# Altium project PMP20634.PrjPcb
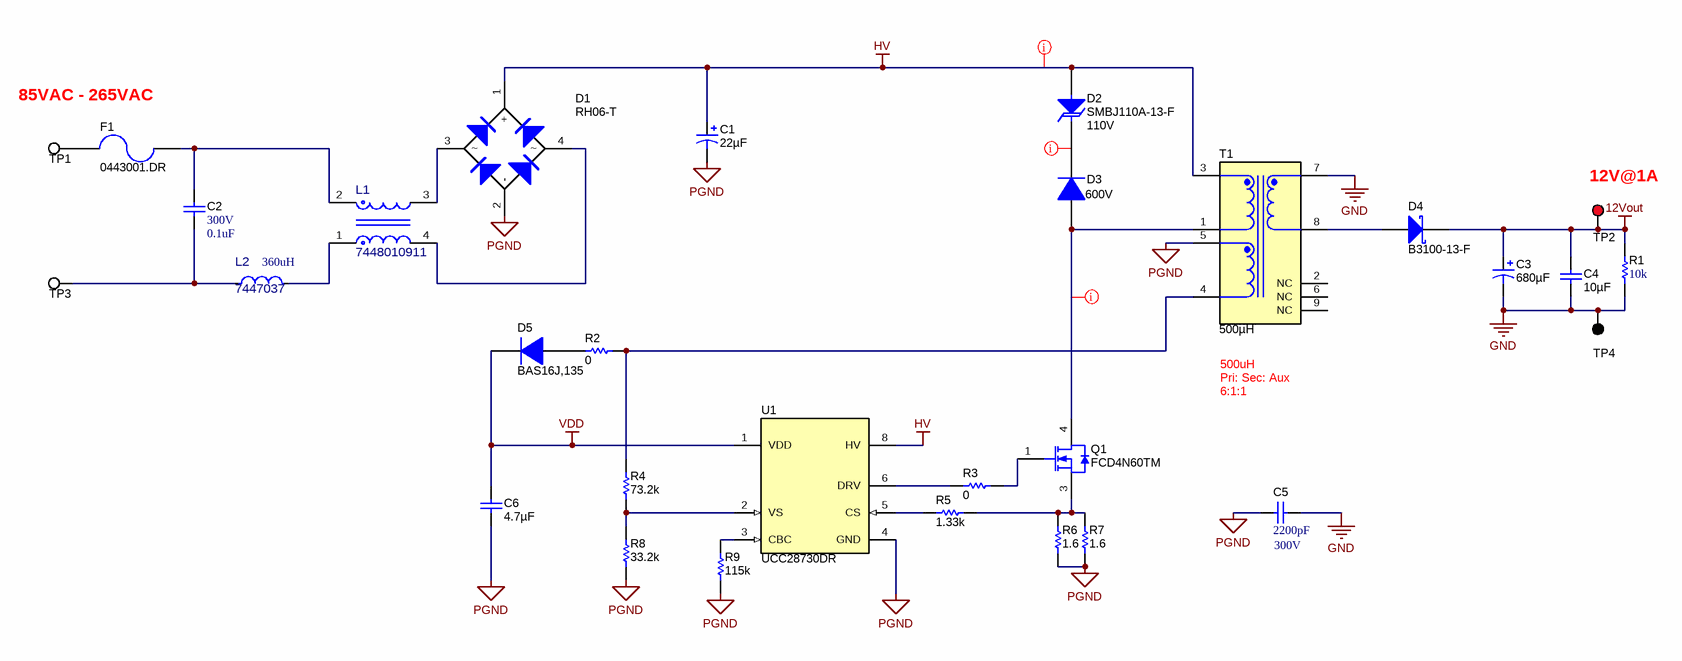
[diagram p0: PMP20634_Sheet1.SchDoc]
TID: N/A; TechSupport: http://www.ti.com/support; SCH_Rev: C; PRJ_Title: 85-265VAC to 12V@1A QR Flyback; PRJ_Number: PMP20634; PRJ_Engineer: C Sarli; PRJ_Customer: Public Release; PCB_Rev: C; PCB_Layout: C Sarli; CopyrightYear: 2016
1 sheet, 30 parts. Net scope: global (net labels, ports and power ports of the same name join across sheets).
Board file: PMP20634.PcbDoc

## Sheet PMP20634_Sheet1.SchDoc
size 431 x 279 mm; Date: Not shown in title block; ApprovedBy: Not shown in title block; CheckedBy: Not shown in title block; Author: Not shown in title block; CompanyName: Not shown in title block; Engineer: Not shown in title block; Organization: Not shown in title block; Address1: Not shown in title block; Address2: Not shown in title block; Address3: Not shown in title block; Address4: Not shown in title block; DocumentNumber: 1; Revision: Use project parameter SCH_Rev; SheetNumber: 1; SheetTotal: 1; PageSetup: Record=PageOptions¦CenterHorizontal=True¦CenterVertical=True¦PrintScale=1.00¦XCorrection=1.00¦YCorrection=1.00¦PrintKind=0¦BorderSize=5000000¦LeftOffset=0¦BottomOffset=0¦Orientation=2¦PaperLength=1000¦PaperWidth=1000¦Scale=100¦PaperSource=15¦PrintQuality=600¦MediaType=1¦DitherType=10¦PaperKind=Letter¦PrintScaleMode=1

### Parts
C1  ValueDisplayed: 22µF  [KXG_1250x2000]  (hidden comment: EKXG401ELL220MK20S)
C2  VDC_V: 300V  ValueDisplayed: 0.1uF  [ECQUG_1500x800x1500]  (hidden comment: ECQ-U3A104MG)
C3  ValueDisplayed: 680µF  [Chemi-Con_1000x2000]  (hidden comment: EKZE250ELL681MJ20S)
C4  ValueDisplayed: 10µF  [0805_HV]  (hidden comment: GRM219R61E106KA12)
C5  VDC_V: 300V  ValueDisplayed: 2200pF  [CAPRD500W60D900H1200]  (hidden comment: VY2222M35Y5US6UV5)
C6  ValueDisplayed: 4.7µF  [0603]  (hidden comment: GRM188R6YA475KE15D)
D1  RH06-T  [MiniDIP]
D2  SMBJ110A-13-F  value 110V  [SMB]
D3  Value2: 600V  [SMA]  (hidden comment: MURA160T3G)
D4  B3100-13-F  [SMC]
D5  BAS16J,135  [SOD-323F]
F1  0443001.DR  [FUSE_0443]
L1  7448010911  [FP-7448010911_PTH_CMC_14MM0_7MM5-MFG]
L2  7447037  value 360uH  [FP-7447037_RADIAL-MFG]
Q1  FCD4N60TM  [DPAK]
R1  ValueDisplayed: 10k  [1206]  (hidden comment: CRCW120610K0JNEA)
R2  ValueDisplayed: 0  [0402]  (hidden comment: CRCW04020000Z0ED)
R3  ValueDisplayed: 0  [0402]  (hidden comment: CRCW04020000Z0ED)
R4  ValueDisplayed: 73.2k  [0402]  (hidden comment: CRCW040273K2FKED)
R5  ValueDisplayed: 1.33k  [0402]  (hidden comment: CRCW04021K33FKED)
R6  ValueDisplayed: 1.6  [0805_HV]  (hidden comment: CRCW08051R60JNEA)
R7  ValueDisplayed: 1.6  [0805_HV]  (hidden comment: CRCW08051R60JNEA)
R8  ValueDisplayed: 33.2k  [0402]  (hidden comment: CRCW040233K2FKED)
R9  ValueDisplayed: 115k  [0402]  (hidden comment: CRCW0402115KFKED)
T1  ValueDisplayed: 500µH  [Wurth_EE16-8-5_5280]  (hidden comment: 750316686)
TP1  5012  [Keystone5012]  (value not drawn)
TP2  5010  [Keystone5010]  (value not drawn)
TP3  5012  [Keystone5012]  (value not drawn)
TP4  5011  [Keystone5011]  (value not drawn)
U1  UCC28730DR  [D0007A_N]

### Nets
12Vout: C3.1(+) C4.1 D4.1(K) R1.2 TP2.1
GND: C3.2(-) C4.2 C5.1 R1.1 T1.7 TP4.1
HV: C1.1(+) D1.1(+) D2.2(A) T1.3 U1.8(HV)
PGND: C1.2(-) C5.2 C6.2 D1.2(-) R6.1 R7.1 R8.1 R9.1 T1.5 U1.4(GND)
VDD: C6.1 D5.1(K) U1.1(VDD)
NetC2_1: C2.1 F1.1 L1.2
NetC2_2: C2.2 L2.1 TP3.1
NetD1_3: D1.3 L1.3
NetD1_4: D1.4 L1.4
NetD2_1: D2.1(K) D3.1(K)
NetD3_2: D3.2(A) Q1.4(D) T1.1
NetD4_2: D4.2(A) T1.8
NetD5_2: D5.2(A) R2.1
NetF1_2: F1.2 TP1.1
NetL1_1: L1.1 L2.2
NetQ1_1: Q1.1(G) R3.2
NetQ1_3: Q1.3(S) R5.2 R6.2 R7.2
NetR2_2: R2.2 R4.2 T1.4
NetR3_1: R3.1 U1.6(DRV)
NetR4_1: R4.1 R8.2 U1.2(VS)
NetR5_1: R5.1 U1.5(CS)
NetR9_2: R9.2 U1.3(CBC)

Not connected (* = marked no-connect by the designer): T1 2(NC) 6(NC) 9(NC)

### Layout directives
rule Undefined: HV, NetD2_1, NetD3_2

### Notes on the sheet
- 85VAC - 265VAC
- (near TP2) 12V@1A
- (near T1) 500uH
- Pri: Sec: Aux
- 6:1:1

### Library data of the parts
C1 = EKXG401ELL220MK20S: CAP, AL, 22 µF, 400 V, +/- 20%, TH; Manufacturer: Chemi-Con; Polarized: Y; CompType: Capacitor; Value: 22uF; U/M: EA; Cap_F: 0.000022; Tolerance_%: 20; Value1: Unknown; VDC_V: 400; Value2: 400V; IRMS_A: 0.26; TaMin_C: -40; TaMax_C: 105; Cap_Case: 12.5x20; SizeAreaWB_mm2: 210.25; SizeArea_mm2: 156.25; SizeX_mm: 12.5; SizeZ_mm: 21.5; AEC Category: Q200
C2 = CMP-0012502-3: CAP, Film, 0.1 uF, 300 V, +/- 20%, TH; Manufacturer: Panasonic; TaMin_C: -40°C; Polarized: N; Value1: Unknown; Value: 0.1uF; TaMax_C: 100°C; Cap_Case: 15x8x15mm; Cap_F: 100nF; AEC Category: Q200
C3 = EKZE250ELL681MJ20S: CAP, AL, 680 µF, 25 V, +/- 20%, TH; Manufacturer: Chemi-Con; Polarized: Y; CompType: Capacitor; Value: 680uF; U/M: EA; Cap_F: 0.00068; Tolerance_%: 20; Value1: Unknown; VDC_V: 25; Value2: 25V; IRMS_A: 1.82; TaMin_C: -40; TaMax_C: 105; Cap_Case: 10x20; SizeAreaWB_mm2: 144; SizeArea_mm2: 100; SizeX_mm: 10; SizeZ_mm: 21.5; AEC Category: Q200; AEC Qualified: N
C4 = GRM219R61E106KA12: CAP, CERM, 10 µF, 25 V, +/- 10%, X5R, 0805; Manufacturer: MuRata; Polarized: N; CompType: Capacitor; Value: 10uF; U/M: EA; Cap_F: 0.00001; Tolerance_%: 10; Value1: Unknown; VDC_V: 25; Value2: 25V; TaMin_C: -55; TaMax_C: 85; Cap_Case: 0805; SizeArea_mm2: 2.5; SizeAreaWB_mm2: 6.75; SizeX_mm: 2; SizeY_mm: 1.25; SizeZ_mm: 1.45; AEC Category: Q200
C5 = CMP-0009628-2: CAP, CERM, 2200pF, 300 V, +/- 20%, Y5U, CAPRD500W60D900H1200; Manufacturer: Vishay-Bccomponents; Cap_F: 22nF; TaMin_C: -40°C; Value1: Unknown; Polarized: N; AEC Category: Q200; Cap_Case: Radial Disc 9mm, ls=10; SizeY_mm: 5; SizeZ_mm: 13; U/M: EA; SizeArea_mm2: 45; SizeX_mm: 9; TaMax_C: 125°C; SizeAreaWB_mm2: 77
C6 = GRM188R6YA475KE15D: CAP, CERM, 4.7 µF, 35 V, +/- 10%, X5R, 0603; Manufacturer: MuRata; Polarized: N; CompType: Capacitor; Value: 4.7uF; U/M: EA; Cap_F: 0.0000047; Tolerance_%: 10; Value1: Unknown; VDC_V: 35; Value2: 35V; TaMin_C: -55; TaMax_C: 85; SizeArea_mm2: 1.28; SizeAreaWB_mm2: 4.68; SizeX_mm: 1.6; SizeY_mm: 0.8; SizeZ_mm: 1; AEC Category: Q200
D1 = RH06-T: Diode, Switching-Bridge, 600 V, 0.5 A, MiniDIP; Manufacturer: Diodes Inc.; U/M: EA; Vf_V: 1.15; Value: 600V; Value1: 0.5A; Value2: 1.15V; Io_A: 0.5; Vr_V: 600; TJmax_C: 150; SizeAreaWB_mm2: 62.1; SizeArea_mm2: 34.3; SizeX_mm: 7; SizeY_mm: 4.9; SizeZ_mm: 3; AEC Category: Q101; AEC Qualified: N
D2 = CMP-0005572-3: Diode, TVS, Uni, 110 V, 177 Vc, SMB; Manufacturer: Diodes Inc.; Value1: 600W; SizeAreaWB_mm2: 44.156; SizeArea_mm2: 21.336; SizeX_mm: 5.6; SizeY_mm: 3.81; SizeZ_mm: 2.6; AEC Category: Q101; Vbr_Max: 140V; Vc: 177V; Ipp: 3.4A; Vbr_Min: 122V
D3 = MURA160T3G: Diode, Ultrafast, 600V, 1A, SMA; Manufacturer: ON Semiconductor; Value: 1.05V; U/M: EA; Vf_V: 1.05; Io_A: 1; Vr_V: 600; TJmax_C: 175
D4 = B3100-13-F: Diode, Schottky, 100 V, 3 A, SMC; Manufacturer: Diodes Inc.; U/M: EA; Vf_V: 0.79; Value: 100V; Value1: 3A; Value2: 0.79V; Io_A: 3; Vr_V: 100; TJmax_C: 125; RJC_CperW: 10; SizeAreaWB_mm2: 83.2686; SizeArea_mm2: 50.5686; SizeX_mm: 8.13; SizeY_mm: 6.22; SizeZ_mm: 2.6; AEC Category: Q101
D5 = BAS16J,135: Diode, Switching, 100 V, 0.25 A, SOD-323F; Manufacturer: NXP Semiconductor; U/M: EA; Value: 100V; Value1: 0.25A; Io_A: 0.25; Vr_V: 100; TJmax_C: 150; SizeAreaWB_mm2: 7.875; SizeArea_mm2: 3.125; SizeX_mm: 2.5; SizeY_mm: 1.25; SizeZ_mm: 0.8; AEC Category: Q101
F1 = 0443001.DR: Fuse, 1 A, 250VAC/VDC, SMD; Manufacturer: Littelfuse; VDC_V: 250; Interrupt_AC: 50; Irating_A: 1; Rtyp_Ohm: 0.18; MeltingTyp: 10.17
L1 = CMP-0091272-1: Common Mode Chokes Dual 11mH 10kHz 900mA 430mOhm DCR Thru-Hole T/R; Manufacturer: Wurth Electronics; DCR_ohm: 0.43; SizeZ_mm: 16mm; AEC Qualified: No; Material: Nanocrystalline; Tolerance_%: +50/-30%
L2 = CMP-0001460-1: 360 µH Unshielded Toroidal Inductor 400 mA 450mOhm Max Radial, Vertical (Open); Manufacturer: Wurth Electronics; Irms: 0.9A; DCR_ohm: 0.45; Material: Ferrite; SizeZ_mm: 13.5mm; Ind_H: 360µH; AEC Qualified: No; TaMax_C: +65°C; TaMin_C: -40°C; Test Frequency: 10kHz; Tolerance_%: 20%
Q1 = FCD4N60TM: MOSFET, N-CH, 600 V, 3.9 A, DPAK; Manufacturer: Fairchild Semiconductor; Alternate Manufacturer: None; U/M: EA; ChType: N; Value: 600V; VdsMax_V: 600; Value1: ? ohm; Value2: 12.8 nC; QgTyp_nC: 12.8; Vgs_V: 30; IdsMax_A: 3.9; SizeAreaWB_mm2: 101.7114; SizeArea_mm2: 64.8114; SizeX_mm: 9.91; SizeY_mm: 6.54; SizeZ_mm: 2.29; AEC Category: Q101
R1 = CMP-0018576-3: RES, 10 k, 5%, 0.25 W, AEC-Q200 Grade 0, 1206; Manufacturer: Vishay-Dale; Power_W: 250mW; TempCo: 200 ppm/C; Value_Code: 10k0; Value: 10k; EIA_Code: E24; SizeX_mm: 3.2; SizeY_mm: 1.6; SizeZ_mm: 1.35; Value2: 0.25W; SizeArea_mm2: 5.12; AEC Qualified: Y; VDC_V: 200V; AEC Category: Q200; AEC Grade: 0
R2 R3 = CRCW04020000Z0ED: RES, 0, 5%, 0.063 W, 0402; Manufacturer: Vishay-Dale; CompType: Resistor; Value: 0; Value_Code: 0000; Tolerance_%: 5; Power_W: 0.063; Value2: 0.063W; VDC_V: 50; TempCo: 200 ppm/C; SizeArea_mm2: 0.5; SizeX_mm: 1; SizeZ_mm: 0.6; EIA_Code: E24; U/M: EA; AEC Category: Q200
R4 = CRCW040273K2FKED: RES, 73.2 k, 1%, 0.063 W, 0402; Manufacturer: Vishay-Dale; CompType: Resistor; Value: 73.2k; Res_ohm: 73200; Value_Code: 73k2; Tolerance_%: 1; Power_W: 0.063; Value2: 0.063W; VDC_V: 50; TempCo: 100 ppm/C; SizeArea_mm2: 0.5; SizeZ_mm: 0.6; EIA_Code: E96; U/M: EA; AEC Category: Q200
R5 = CRCW04021K33FKED: RES, 1.33 k, 1%, 0.063 W, 0402; Manufacturer: Vishay-Dale; CompType: Resistor; Value: 1.33k; Res_ohm: 1330; Value_Code: 1k33; Tolerance_%: 1; Power_W: 0.063; Value2: 0.063W; VDC_V: 50; TempCo: 100 ppm/C; SizeArea_mm2: 0.5; SizeZ_mm: 0.6; EIA_Code: E96; U/M: EA; AEC Category: Q200
R6 R7 = CRCW08051R60JNEA: RES, 1.6, 5%, 0.125 W, 0805; Manufacturer: Vishay-Dale; CompType: Resistor; Value: 1.6; Value_Code: 1R60; Tolerance_%: 5; Power_W: 0.125; Value2: 0.125W; VDC_V: 150; TempCo: 200 ppm/C; SizeArea_mm2: 2.5; SizeX_mm: 2; SizeY_mm: 1.25; SizeZ_mm: 1.45; EIA_Code: E24; U/M: EA; AEC Category: Q200
R8 = CRCW040233K2FKED: RES, 33.2 k, 1%, 0.063 W, 0402; Manufacturer: Vishay-Dale; CompType: Resistor; Value: 33.2k; Res_ohm: 33200; Value_Code: 33k2; Tolerance_%: 1; Power_W: 0.063; Value2: 0.063W; VDC_V: 50; TempCo: 100 ppm/C; SizeArea_mm2: 0.5; SizeZ_mm: 0.6; EIA_Code: E96; U/M: EA; AEC Category: Q200
R9 = CRCW0402115KFKED: RES, 115 k, 1%, 0.063 W, 0402; Manufacturer: Vishay-Dale; CompType: Resistor; Value: 115k; Res_ohm: 115000; Tolerance_%: 1; Power_W: 0.063; Value2: 0.063W; VDC_V: 50; TempCo: 100 ppm/C; SizeArea_mm2: 0.5; SizeZ_mm: 0.6; EIA_Code: E96; U/M: EA; AEC Category: Q200
T1 = 750316686: Transformer, 500 uH, EE16/8/5, TH; Manufacturer: Wurth Elektronik; SymbolCreator: a0411947; Value: 500uH; Lp: 500; DCR_ohm: 0.64; LeakageL: 20; Ns1toNp: 1.67; Rs1: 0.035; SizeAreaWB_mm2: 572; SizeArea_mm2: 480; SizeX_mm: 24; SizeZ_mm: 16
TP1 TP3 = 5012: Test Point, Multipurpose, White, TH; Manufacturer: Keystone; CompType: Test Point Loop; ContactFinish: Silver
TP2 = 5010: Test Point, Multipurpose, Red, TH; Manufacturer: Keystone; CompType: Test Point Loop; ContactFinish: Silver
TP4 = 5011: Test Point, Multipurpose, Black, TH; Manufacturer: Keystone; CompType: Test Point Loop; ContactFinish: Silver
U1 = UCC28730DR: Constant-Voltage Constant-Current Flyback Controller With PSR and Wake-Up Monitoring, D0007A (SOIC-7); Manufacturer: Texas Instruments; SymbolCreator: x0208325; SizeArea_mm2: 29.4; SizeAreaWB_mm2: 55.2; SizeX_mm: 6; SizeY_mm: 4.9; SizeZ_mm: 1.75; CompType: IC; U/M: EA

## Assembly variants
001: not fitted Q2 R7 R9 R16 R17 R18 TP6 U4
